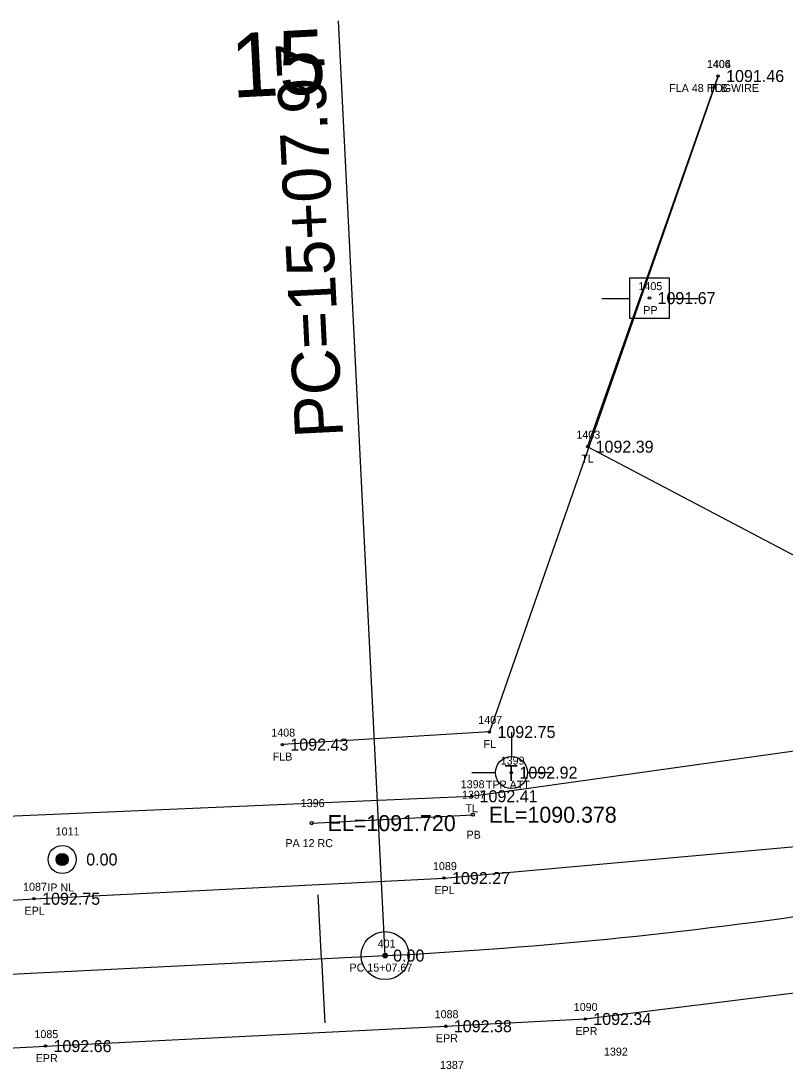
# Model space of a CAD drawing. Extents: x 1539151 to 1541799, y 1198646 to 1201165.
# Drawn here: x 1539855.3 to 1539950.8, y 1199362.5 to 1199492.6 of the extents above; entities that cross this region are included whole.
import ezdxf

# ---------------------------------------------------------------- set-up
doc = ezdxf.new("R2010")
doc.units = 0
for name, color, linetype in [('RD_EX_DR_Pipe', 7, 'Continuous'), ('RD_EX_DR_Pipe_txCode', 7, 'Continuous'), ('RD_EX_DV_Prop_txCode', 7, 'Continuous'), ('RD_EX_DV_PropPin', 7, 'Continuous'), ('RD_EX_Fence_Other', 7, 'Continuous'), ('RD_EX_Fence_Other_txCode', 7, 'Continuous'), ('RD_EX_Road', 7, 'Continuous'), ('RD_EX_Road_txCode', 7, 'Continuous'), ('RD_EX_TX_DV_Prop_ELEV', 7, 'Continuous'), ('RD_EX_TX_Fence_Other_ELEV', 7, 'Continuous'), ('RD_EX_TX_Road_ELEV', 7, 'Continuous'), ('RD_EX_TX_UT_ELEV', 7, 'Continuous'), ('RD_EX_TX_VEG_ELEV', 7, 'Continuous'), ('RD_EX_UT', 7, 'Continuous'), ('RD_EX_UT_txCode', 7, 'Continuous'), ('RD_EX_VEG', 7, 'Continuous'), ('RD_EX_VEG_txCode', 7, 'Continuous'), ('RD_HC_Cl', 7, 'Continuous'), ('RD_HC_Data', 7, 'Continuous'), ('RD_HC_Data_Tic', 7, 'Continuous'), ('RD_HC_Survey_ELEV', 7, 'Continuous'), ('RD_HC_TX_Sta50', 7, 'Continuous'), ('RD_HC_txCode', 7, 'Continuous'), ('RD_SMD_Locator', 7, 'Continuous'), ('RD_TX_Pipe_ElevEX', 7, 'Continuous')]:
    doc.layers.add(name, color=color, linetype=linetype)

msp = doc.modelspace()

# ---------------------------------------------------------------- linework, layer by layer
at = {"layer": 'RD_EX_DR_Pipe'}
msp.add_line((1539891.69, 1199392.32), (1539911.81, 1199393.37), dxfattribs=at)
at = {"layer": 'RD_EX_DV_PropPin'}
for p, q in [((1539859.79, 1199387.58), (1539859.79, 1199387.97)), ((1539859.82, 1199387.48), (1539859.82, 1199388.08)), ((1539859.86, 1199387.41), (1539859.86, 1199388.15)), ((1539859.89, 1199387.35), (1539859.89, 1199388.2)), ((1539859.93, 1199387.3), (1539859.93, 1199388.25)), ((1539859.96, 1199387.26), (1539859.96, 1199388.29)), ((1539860, 1199387.23), (1539860, 1199388.33)), ((1539860.03, 1199387.2), (1539860.03, 1199388.36)), ((1539860.07, 1199387.17), (1539860.07, 1199388.39)), ((1539860.1, 1199387.14), (1539860.1, 1199388.41)), ((1539860.14, 1199387.12), (1539860.14, 1199388.43)), ((1539860.17, 1199387.1), (1539860.17, 1199388.45)), ((1539860.21, 1199387.09), (1539860.21, 1199388.47)), ((1539860.24, 1199387.07), (1539860.24, 1199388.49)), ((1539860.28, 1199387.06), (1539860.28, 1199388.5)), ((1539860.31, 1199387.05), (1539860.31, 1199388.51)), ((1539860.35, 1199387.04), (1539860.35, 1199388.52)), ((1539860.38, 1199387.03), (1539860.38, 1199388.53)), ((1539860.42, 1199387.02), (1539860.42, 1199388.53)), ((1539860.45, 1199387.02), (1539860.45, 1199388.54)), ((1539860.49, 1199387.02), (1539860.49, 1199388.54)), ((1539860.52, 1199387.02), (1539860.52, 1199388.54)), ((1539860.56, 1199387.02), (1539860.56, 1199388.54)), ((1539860.59, 1199387.02), (1539860.59, 1199388.54)), ((1539860.63, 1199387.02), (1539860.63, 1199388.53)), ((1539860.66, 1199387.03), (1539860.66, 1199388.53)), ((1539860.7, 1199387.04), (1539860.7, 1199388.52)), ((1539860.73, 1199387.05), (1539860.73, 1199388.51)), ((1539860.77, 1199387.06), (1539860.77, 1199388.5)), ((1539860.8, 1199387.07), (1539860.8, 1199388.49)), ((1539860.84, 1199387.09), (1539860.84, 1199388.47)), ((1539860.87, 1199387.1), (1539860.87, 1199388.45)), ((1539860.91, 1199387.12), (1539860.91, 1199388.43)), ((1539860.94, 1199387.14), (1539860.94, 1199388.41)), ((1539860.98, 1199387.17), (1539860.98, 1199388.39)), ((1539861.01, 1199387.2), (1539861.01, 1199388.36)), ((1539861.05, 1199387.23), (1539861.05, 1199388.33)), ((1539861.08, 1199387.26), (1539861.08, 1199388.29)), ((1539861.12, 1199387.3), (1539861.12, 1199388.25)), ((1539861.15, 1199387.35), (1539861.15, 1199388.2)), ((1539861.19, 1199387.41), (1539861.19, 1199388.15)), ((1539861.22, 1199387.48), (1539861.22, 1199388.08)), ((1539861.26, 1199387.58), (1539861.26, 1199387.97))]:
    msp.add_line(p, q, dxfattribs=at)
for radius in [1.75, 0.761]:
    msp.add_circle((1539860.52, 1199387.78), radius, dxfattribs=at)
at = {"layer": 'RD_EX_Fence_Other'}
msp.add_lwpolyline([(1539942.46, 1199485.66), (1539913.89, 1199403.71), (1539888.02, 1199402.13)], dxfattribs=at)
at = {"layer": 'RD_EX_Road'}
for points in [[(1539428.76, 1199454.93), (1539416.46, 1199395.23), (1539420.91, 1199377.84), (1539428.29, 1199368.53), (1539440.24, 1199363.06), (1539462.84, 1199364.11), (1539506.12, 1199366.59), (1539554.03, 1199368.02), (1539606.53, 1199370.48), (1539651.89, 1199372.76), (1539672.94, 1199372.91), (1539707.02, 1199374.85), (1539748.7, 1199377.62), (1539769.05, 1199378.19), (1539812.94, 1199380.16), (1539830.48, 1199381.23), (1539857.01, 1199382.87), (1539908.22, 1199385.45), (1539955.82, 1199389.74), (1539996.13, 1199397.4), (1540037.85, 1199410.51), (1540050.26, 1199415.61), (1540093.12, 1199444.78)], [(1539376.14, 1199238.5), (1539389.65, 1199292.82), (1539395.62, 1199315.5), (1539405.98, 1199330.34), (1539420.48, 1199338.44), (1539434.13, 1199341.92), (1539458.27, 1199343.35), (1539505.21, 1199345.92), (1539518.44, 1199346.66), (1539558.02, 1199348.62), (1539607.46, 1199351.19), (1539654.3, 1199353.64), (1539676.57, 1199355), (1539708.42, 1199356.93), (1539757.47, 1199359.08), (1539779.44, 1199360.44), (1539802.8, 1199361.54), (1539858.43, 1199364.46), (1539908.44, 1199366.95), (1539925.86, 1199367.85), (1539963.35, 1199372.53)]]:
    msp.add_lwpolyline(points, dxfattribs=at)
at = {"layer": 'RD_EX_UT'}
for p, q in [((1539936.38, 1199460.42), (1539931.38, 1199460.42)), ((1539931.38, 1199460.42), (1539931.38, 1199455.42)), ((1539936.38, 1199455.42), (1539936.38, 1199460.42)), ((1539927.95, 1199457.85), (1539931.42, 1199457.85)), ((1539936.31, 1199457.85), (1539939.95, 1199457.85)), ((1539931.38, 1199455.42), (1539936.38, 1199455.42)), ((1539916.64, 1199403.7), (1539916.64, 1199400.63)), ((1539911.71, 1199398.64), (1539914.64, 1199398.64)), ((1539918.64, 1199398.64), (1539921.71, 1199398.64))]:
    msp.add_line(p, q, dxfattribs=at)
msp.add_circle((1539916.64, 1199398.63), 2, dxfattribs=at)
at = {"layer": 'RD_EX_VEG'}
msp.add_lwpolyline([(1539846.78, 1199470.02), (1539829.4, 1199392.14), (1539911.66, 1199395.68), (1539954.64, 1199401.74), (1539995.07, 1199408.66), (1539952.34, 1199425.54), (1539926.15, 1199439.35), (1539942.46, 1199485.66)], dxfattribs=at)
at = {"layer": 'RD_HC_Cl'}
msp.add_line((1539393.53, 1199350.4), (1539900.86, 1199375.77), dxfattribs=at)
msp.add_arc((1539872.5, 1199943.1), 568.04, 272.8619, 284.8221, dxfattribs=at)
at = {"layer": 'RD_HC_Data'}
msp.add_line((1539900.86, 1199375.77), (1539895.02, 1199492.55), dxfattribs=at)
for radius in [3, 0.282]:
    msp.add_circle((1539900.86, 1199375.77), radius, dxfattribs=at)
at = {"layer": 'RD_HC_Data_Tic'}
for q in [(1539892.51, 1199383.36), (1539893.31, 1199367.38)]:
    msp.add_line((1539892.91, 1199375.37), q, dxfattribs=at)
at = {"layer": 'RD_SMD_Locator'}
for centre, radius in [((1539942.46, 1199485.66), 0.15), ((1539942.46, 1199485.66), 0.15), ((1539933.89, 1199457.91), 0.15), ((1539926.15, 1199439.35), 0.15), ((1539913.89, 1199403.71), 0.15), ((1539888.02, 1199402.13), 0.15), ((1539916.64, 1199398.63), 0.15), ((1539911.66, 1199395.68), 0.15), ((1539911.81, 1199393.37), 0.2), ((1539891.69, 1199392.32), 0.2), ((1539860.52, 1199387.78), 0.15), ((1539908.22, 1199385.45), 0.15), ((1539857.01, 1199382.87), 0.15), ((1539900.86, 1199375.77), 0.15), ((1539908.44, 1199366.95), 0.15), ((1539925.86, 1199367.85), 0.15), ((1539858.43, 1199364.46), 0.15)]:
    msp.add_circle(centre, radius, dxfattribs=at)

# ---------------------------------------------------------------- texts
at = {"layer": 'RD_EX_DR_Pipe_txCode'}
for s, p in [('1397', (1539910.46, 1199395.37)), ('1396', (1539890.32, 1199394.32)), ('PB', (1539911.03, 1199390.37)), ('PA 12 RC', (1539888.4, 1199389.32)), ('1392', (1539928.2, 1199363.27)), ('1387', (1539907.71, 1199361.61))]:
    msp.add_text(s, height=1, dxfattribs=at).set_placement(p)
at = {"layer": 'RD_EX_DV_Prop_txCode'}
for s, p in [('1011', (1539859.7, 1199390.78)), ('IP NL', (1539858.66, 1199383.78))]:
    msp.add_text(s, height=1, dxfattribs=at).set_placement(p)
at = {"layer": 'RD_EX_Fence_Other_txCode'}
for s, p in [('1406', (1539941.05, 1199486.66)), ('FLA 48 HOGWIRE', (1539936.35, 1199483.66)), ('1407', (1539912.5, 1199404.71)), ('1408', (1539886.64, 1199403.13)), ('FL', (1539913.16, 1199401.71)), ('FLB', (1539886.82, 1199400.13))]:
    msp.add_text(s, height=1, dxfattribs=at).set_placement(p)
at = {"layer": 'RD_EX_Road_txCode'}
for s, p in [('1089', (1539906.84, 1199386.45)), ('1087', (1539855.63, 1199383.87)), ('EPL', (1539907.02, 1199383.45)), ('EPL', (1539855.81, 1199380.87)), ('1090', (1539924.43, 1199368.85)), ('1088', (1539907.05, 1199367.95)), ('1085', (1539857.05, 1199365.46)), ('EPR', (1539907.21, 1199364.95)), ('EPR', (1539924.63, 1199365.85)), ('EPR', (1539857.21, 1199362.46))]:
    msp.add_text(s, height=1, dxfattribs=at).set_placement(p)
at = {"layer": 'RD_EX_TX_DV_Prop_ELEV'}
msp.add_text('0.00', height=1.5, dxfattribs=at).set_placement((1539863.52, 1199387.03))
at = {"layer": 'RD_EX_TX_Fence_Other_ELEV'}
for s, p in [('1091.46', (1539943.46, 1199484.91)), ('1092.75', (1539914.89, 1199402.96)), ('1092.43', (1539889.02, 1199401.38))]:
    msp.add_text(s, height=1.5, dxfattribs=at).set_placement(p)
at = {"layer": 'RD_EX_TX_Road_ELEV'}
for s, p in [('1092.27', (1539909.22, 1199384.7)), ('1092.75', (1539858.01, 1199382.12)), ('1092.34', (1539926.86, 1199367.1)), ('1092.38', (1539909.44, 1199366.2)), ('1092.66', (1539859.43, 1199363.71))]:
    msp.add_text(s, height=1.5, dxfattribs=at).set_placement(p)
at = {"layer": 'RD_EX_TX_UT_ELEV'}
msp.add_text('1092.92', height=1.5, dxfattribs=at).set_placement((1539917.64, 1199397.88))
at = {"layer": 'RD_EX_TX_VEG_ELEV'}
for s, p in [('1091.46', (1539943.46, 1199484.91)), ('1092.39', (1539927.15, 1199438.6)), ('1092.41', (1539912.66, 1199394.93))]:
    msp.add_text(s, height=1.5, dxfattribs=at).set_placement(p)
at = {"layer": 'RD_EX_UT'}
msp.add_text('T', height=2, dxfattribs=at).set_placement((1539915.79, 1199397.58))
at = {"layer": 'RD_EX_UT_txCode'}
for s, p in [('1405', (1539932.51, 1199458.91)), ('PP', (1539933.11, 1199455.91)), ('1399', (1539915.3, 1199399.63)), ('TPP ATT', (1539913.44, 1199396.63))]:
    msp.add_text(s, height=1, dxfattribs=at).set_placement(p)
at = {"layer": 'RD_EX_VEG_txCode'}
for s, p in [('1404', (1539941.08, 1199486.66)), ('TLB', (1539941.22, 1199483.66)), ('1403', (1539924.76, 1199440.35)), ('TL', (1539925.37, 1199437.35)), ('1398', (1539910.31, 1199396.68)), ('TL', (1539910.89, 1199393.68))]:
    msp.add_text(s, height=1, dxfattribs=at).set_placement(p)
at = {"layer": 'RD_HC_Data'}
msp.add_text('PC=15+07.97', height=6, rotation=92.8619, dxfattribs=at).set_placement((1539895.62, 1199440.59))
at = {"layer": 'RD_HC_Survey_ELEV'}
for s, p in [('1091.67', (1539934.89, 1199457.16)), ('0.00', (1539901.86, 1199375.02))]:
    msp.add_text(s, height=1.5, dxfattribs=at).set_placement(p)
at = {"layer": 'RD_HC_TX_Sta50'}
msp.add_text('15', height=8, rotation=2.8619, dxfattribs=at).set_placement((1539881.76, 1199482.95))
at = {"layer": 'RD_HC_txCode'}
for s, p in [('401', (1539899.93, 1199376.77)), ('PC 15+07.67', (1539896.41, 1199373.77))]:
    msp.add_text(s, height=1, dxfattribs=at).set_placement(p)
at = {"layer": 'RD_TX_Pipe_ElevEX'}
for s, p in [('EL=1090.378', (1539913.81, 1199392.37)), ('EL=1091.720', (1539893.69, 1199391.32))]:
    msp.add_text(s, height=2, dxfattribs=at).set_placement(p)

doc.saveas('drawing.dxf')
